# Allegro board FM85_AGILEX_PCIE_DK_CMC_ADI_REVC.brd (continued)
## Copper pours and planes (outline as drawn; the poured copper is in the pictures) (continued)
3P3V on L12_SIG4: 199.52,98.89 199.88,98.53 202.68,98.53 204.88,96.34 214.4,96.34 215.06,97.01 215.06,107.45 212.45,110.06 22.59,110.06 22.47,109.94 22.47,107.81 22.91,107.38 26.64,107.38 28.18,108.92 30.35,108.92 30.74,108.53 54.43,108.53 55.03,107.94 97.07,107.94 97.61,107.39 145.81,107.39 146.22,107.81 198.64,107.81 199.52,106.93
3P3V on L12_SIG4: 66.3,49.68 66.87,49.11 66.87,48.07 65.64,46.85 64.04,46.85 63.76,46.57 63.76,46.17 65.03,44.9 65.03,44.01 63.91,42.9 62.36,42.9 53.5,34.04 47.49,34.04 46.62,33.16 46.62,29.13 48.72,29.13 49.28,29.69 50.93,29.69 50.93,29.7 55.81,29.7 55.81,29.69 59.35,29.69 65.21,35.56 76.85,35.56 79.38,38.09 79.38,40.37 81.4,42.39 83.1,42.39 87.68,46.97 87.68,47.59 80.3,54.97 79.8,54.97 79.8,61.21 79.44,61.57 79.38,61.57 79.38,65.99 77.06,68.31 77.06,69.2 75.94,70.31 71.15,70.31 67.13,74.33 67.13,82.62 70.29,85.78 70.29,87.12 70.38,87.22 70.38,90.54 65.66,95.27 36.47,95.27 34.63,93.43 34.63,84.41 35.95,83.09 42.72,83.09 43.99,84.37 58.84,84.37 59.12,84.09 59.12,78.56 51,78.56 48.89,76.45 48.89,60.58 50.84,58.63 57.83,58.63 59.12,57.34 59.12,51.68 61.12,49.68
3P3V on L12_SIG4: 224.55,45.2 226.41,47.06 226.41,55.37 227.56,56.52 236.79,56.52 238.01,55.3 238.01,49.38 237.15,48.53 234.35,48.53 231.61,45.78 231.61,37.77 239.45,29.93 239.45,20.43 239.06,20.04 237.72,20.04 237.27,20.48 237.27,27.26 229.83,34.71 225.47,34.71 224.55,35.63
3P3V on L14_SIG5: 222.89,50.12 222.89,22.34 223.59,21.65 239.42,21.65 241.76,23.98 241.76,34.03 244.36,36.63 244.36,48.34 239.15,53.55 226.32,53.55
3P3V_AGND on TOP: 236.94,36.4 236.94,37.32 236.56,37.7 235.74,37.7 235.49,37.95 235.49,38.43 235.47,38.46 234.83,38.46 234.8,38.43 234.8,37.39 234.65,37.24 233.66,37.24 233.51,37.39 233.51,38.38 233.43,38.46 231.76,38.46 231.68,38.38 231.68,36.48 231.83,36.32 236.86,36.32
3P3V_STBY on TOP: 225.2,36.32 228.1,36.32 229.24,35.18 235.87,35.18 237.32,33.73 243.03,33.73 244.1,32.67 251.04,32.67 251.49,33.12 251.49,33.66 250.96,34.19 246.01,34.19 245.93,34.11 244.18,34.11 243.42,34.88 237.7,34.88 236.48,36.1 229.32,36.1 228.02,37.39 225.51,37.39 225.2,37.09
3P3V_STBY on TOP: 20.58,43.44 20.58,41.35 20.99,40.95 21.62,40.95 21.75,40.82 21.75,39.98 21.95,39.78 23.55,39.78 24.04,40.26 24.04,41.96 24.31,42.24 25.18,42.24 25.36,42.42 25.36,43.16 25.18,43.34 23.76,43.34 23.2,43.89 21.04,43.89
3P3V_STBY on BOTTOM: 21.32,47.15 21.32,44.2 20.66,43.54 20.66,41.28 22.64,39.3 23.38,39.3 23.38,39.96 23.5,40.08 23.5,47.12 23.35,47.27 21.44,47.27
3P3V_STBY on L05_SIG2: 251.85,99.39 241.31,109.93 13.59,109.93 13.57,109.91 12.46,109.91 11.93,109.38 11.93,43.17 15.06,40.04 27.73,40.04 29.72,42.03 29.72,58.86 28.33,60.25 28.33,62.56 26.86,64.02 26.93,64.09 26.93,104.09 30.49,107.65 39.25,107.65 39.63,107.27 92.59,107.27 93.86,108.54 167.9,108.54 169.04,107.39 195.03,107.39 195.18,107.24 195.18,93.78 193.28,91.87 168.13,91.87 167.6,91.34 167.6,88.75 167.68,88.66 202.36,88.66 203.61,87.41 209.88,87.41 210.78,86.51 210.78,84.88 211.5,84.16 214.21,84.16 214.56,84.52 214.56,90.25 211.14,93.67 206.05,93.67 205.25,94.47 205.25,103.82 206.05,104.61 208.15,104.61 208.54,104.22 227.72,104.22 229.5,106 242.07,106 249.56,98.5 249.56,82.63 248.42,81.49 242.7,81.49 238.64,77.42 238.64,72.21 240.04,70.82 242.83,70.82 243.65,70 243.65,30.91 244.2,30.36 244.2,29.35 238.35,23.51 217.19,23.51 213.33,19.65 202.14,19.65 201.52,20.27 198.85,20.27 198.4,19.82 198.4,18.88 196.48,16.96 196.48,15 196.65,14.84 224.14,14.84 225.58,16.28 243.64,16.28 251.85,24.49
3P3V_STBY on L12_SIG4: 229.19,96.07 232.72,96.07 232.98,96.32 232.98,104.79 233.45,105.26 233.45,106.62 233.03,107.04 229.19,107.04 228.94,106.78 228.94,96.32
3P3V_STBY on L14_SIG5: outline of 88 points within 2.04,11.13 77.53,86.1
3P3V_USBPHY on L09_PWR1: 19.82,35.26 1.66,35.26 1.28,34.88 1.28,14.56 1.66,14.18 19.7,14.18 20.2,14.68 20.2,34.88
3P3V_USBPHY on L12_SIG4: 6.05,33.81 6.05,29.92 8.87,27.1 8.87,22.46 11.77,19.56 19.69,19.56 20.68,20.55 20.68,25.58 29.29,34.19 36.46,34.19 37.14,34.88 37.14,36.1 37.1,36.13 37.1,37.41 36.39,38.12 30.4,38.12 27.16,34.88 26.32,34.88 22.74,31.3 20.68,31.3 17.03,34.95 7.2,34.95
CH01_RUN on L16_SIG6: 186.91,25.16 186.91,23.41 187.31,23.01 187.88,23.01 188.04,23.16 188.04,23.86 188.41,24.24 190.39,24.24 190.9,23.74 190.9,23.55 191.09,23.36 191.72,23.36 191.93,23.56 191.93,23.99 192.91,24.98 192.91,25.28 192.56,25.63 187.38,25.63
CH02_RUN on L03_SIG1: 208.77,98.33 208.77,97.38 209.02,97.13 211.04,97.13 211.2,97.28 212.25,97.28 212.41,97.13 214.87,97.13 215.08,97.34 215.84,97.34 216.05,97.13 216.86,97.13 217.54,96.46 218.09,96.46 218.39,96.76 218.39,97.16 217.99,97.55 217.65,97.55 217.14,98.06 217.14,98.34 217.1,98.38 216.46,98.38 216.35,98.27 216.35,98.03 216.17,97.85 214.94,97.85 214.67,97.58 213.32,97.58 213.06,97.84 213.06,98.24 212.95,98.35 212.69,98.35 212.56,98.22 212.56,98 212.43,97.87 211.13,97.87 210.95,97.7 209.35,97.7 209.3,97.75 209.3,98.36 209.22,98.44 208.87,98.44
COMP_0P8 on L12_SIG4: 70.05,72.87 70.05,72.56 71.52,71.09 75.81,71.09 75.81,71.5 74.98,72.33 71.17,72.33 70.52,72.99 70.17,72.99
FGT_AGND on BOTTOM: 38.13,106.73 38.13,105.9 38.36,105.67 43.01,105.67 44.91,103.76 45.52,103.76 45.68,103.91 45.68,106.12 44.91,106.89 38.28,106.89
FPGA_VCC on TOP: 155.27,92 161.55,92 161.98,91.57 161.98,31.65 161.14,30.81 142.76,30.81 142.37,31.19 87.64,31.19 85.39,33.44 85.39,89.91 86.88,91.39 146.78,91.39 147.62,90.55 147.62,90.51 148.01,90.12 154.62,90.12 154.93,90.44 154.93,91.67 ; 9 cut-outs
FPGA_VCC on BOTTOM: 119.01,34.5 119.01,32.34 118.88,32.21 117.61,32.21 117.48,32.34 117.48,34.5 117.61,34.62 118.88,34.62
FPGA_VCC on BOTTOM: 115.45,53.67 115.45,54.69 117.99,54.69 118.12,54.56 118.12,53.42 118.29,53.24 119.51,53.24 119.67,53.09 119.82,53.24 119.82,53.93 120.05,54.16 122.03,54.16 122.49,53.7 123.02,53.7 123.02,53.39 123.17,53.24 123.55,53.24 123.93,52.86 123.93,51.95 123.63,51.64 122.94,51.64 122.1,50.8 121.8,50.8 120.43,49.43 119.36,49.43 119.13,49.66 118.6,49.66 118.29,49.35 117.76,49.35 117.46,49.66 117,49.66 116.69,49.35 116.16,49.35 115.7,49.81 115.55,49.81 115.17,49.43 114.56,49.43 114.18,49.81 113.88,49.81 113.42,49.35 113.04,49.35 112.5,49.89 112.5,50.65 112.81,50.96 113.65,50.96 113.88,51.18 113.88,51.41 113.57,51.72 113.57,52.17 113.8,52.4 114.18,52.4
FPGA_VCC on BOTTOM: 144.91,71.33 144.91,72.6 144.3,73.21 144.3,89.92 154.62,89.92 156.83,92.13 158.71,92.13 158.99,91.85 158.99,90.58 159.11,90.45 159.11,30.99 157.3,30.99 156.91,31.38 154.56,31.38 154.36,31.57 154.36,38.38 150.76,41.99 150.76,45.16 151.26,45.67 154.19,45.67 154.44,45.93 154.44,49.46 152.79,51.11 152.79,56.34 152.53,56.59 151.77,56.59 151.39,56.97 151.39,64.09 150.76,64.72 149.74,64.72 149.36,65.1 149.36,67.52 148.34,68.53 148.34,70.56 147.94,70.97 145.27,70.97
FPGA_VCC on BOTTOM: 112.5,54.16 112.5,65.05 111.67,65.89 110.9,65.89 110.07,66.73 109.91,66.73 109.53,66.35 109.53,64.37 108.76,64.37 108.76,62.93 109.38,62.31 109.38,62 108.69,61.32 108.69,59.95 107.93,59.18 107.93,58.8 108.16,58.58 108.16,58.27 107.93,58.04 107.93,55.15 108.31,54.77 108.31,54.08 107.93,53.7 107.93,52.94 109.53,51.34 111.44,51.34 113.42,53.32 113.42,53.7 113.27,53.85 112.81,53.85
FPGA_VCC on BOTTOM: 131.58,86.76 129.8,86.76 129.8,85.04 130.06,84.79 131.33,84.79 131.58,85.04
FPGA_VCC on BOTTOM: 120.53,55.07 120.53,64.59 120.45,64.67 119.82,64.67 119.21,65.28 119.21,65.36 120.12,66.27 120.5,66.27 121.04,66.8 121.5,66.8 121.88,67.19 122.1,67.19 122.41,67.49 123.32,67.49 124.01,66.8 126.19,66.8 126.19,63.47 125.94,63.22 123.98,63.22 123.61,62.85 123.61,61.88 123.95,61.88 125.05,60.78 125.05,59.75 123.76,58.46 123.76,57.79 123.88,57.67 124.09,57.67 124.84,56.92 124.84,54.45 124.39,54 124.16,54 123.63,54.54 121.72,54.54 121.55,54.71 120.89,54.71
FPGA_VCC on BOTTOM: 117.36,64.09 114.93,64.09 114.77,64.25 114.77,64.62 114.52,64.87 114.52,64.9 114.48,64.9 113.49,65.89 112.96,65.89 112.5,66.35 112.28,66.35 111.74,66.88 111.36,66.88 111.21,67.03 111.21,67.34 111.89,68.02 112.81,68.02 114.18,69.4 114.94,69.4 115.25,69.09 115.93,69.09 116.16,69.32 116.54,69.32 116.77,69.09 117.38,69.09 117.76,69.47 118.07,69.47 118.52,69.01 118.98,69.01 119.29,69.32 119.74,69.32 120.05,69.01 120.5,69.01 120.89,69.4 121.34,69.4 121.57,69.17 121.57,69.01 121.34,68.79 121.34,68.02 121.11,67.8 120.66,67.8 120.58,67.72 120.58,67.49 120.5,67.41 119.9,67.41 119.82,67.34 119.82,67.26 119.06,66.5 118.37,66.5 118.22,66.35 118.22,66.04 117.36,65.18
FPGA_VCC on L09_PWR1: 170.7,91.52 170.7,44.1 158.66,32.06 110.57,32.06 110.5,32.13 110.5,37.04 108.21,39.32 108.21,59.01 108.97,59.77 108.97,65.99 108.59,66.37 105.67,66.37 105.29,66.75 105.29,74.88 96.67,83.5 96.67,86.69 97.4,87.41 106.38,87.41 107.32,86.47 107.32,79.99 110.37,76.94 110.37,69.47 110.52,69.32 123.48,69.32 123.86,69.7 123.86,89.08 126.68,91.9 170.31,91.9
GXR_AGND on BOTTOM: 210.19,36.4 210.19,32.51 209.96,32.29 208.74,32.29 208.44,32.59 208.44,33.96 208.29,34.11 208.29,34.34 208.44,34.5 209.13,34.5 209.32,34.69 209.32,36.52 210.34,37.54 210.57,37.54 210.8,37.32 210.8,37.01
HSSI_GXF_AGND on TOP: 69.63,72.06 69.63,70.39 69.7,70.31 71.58,70.31 71.66,70.39 71.66,72.06 71.52,72.2 69.77,72.2
HSSI_GXF_AGND on L14_SIG5: 75.01,67.11 75.01,67.12 75.07,67.18 75.58,67.18 76.58,68.18 76.58,71.64 75.75,72.46 71.64,72.46 71.64,72.37 69.94,72.37 69.9,72.41 68.43,72.41 68.05,72.03 68.05,67.96 68.89,67.11
IIN-_0 on TOP: 189.08,43 188.6,42.52 188.6,38.41 188.81,38.2 193.1,38.2 193.12,38.23 195.51,38.23 195.66,38.38 195.66,41 194.67,41.99 194.67,42.95 194.49,43.13 193.58,43.13 193.45,43
IIN-_0 on BOTTOM: 186.8,43.18 186.72,43.11 186.72,41.89 187.13,41.48 187.13,39.37 186.72,39.37 186.57,39.22 186.57,38.31 186.65,38.23 188.4,38.23 188.63,38 195.51,38 195.82,38.31 196.4,38.31 196.45,38.36 196.45,43.36 196.25,43.56 195.94,43.56 195.79,43.41 195.79,42.42 195.56,42.19 194.8,42.19 194.62,42.37 194.62,43.18
INTVCC4 on BOTTOM: 42.48,102.39 42.48,104.14 41.64,104.98 38.06,104.98 37.98,104.9 37.29,104.9 37.29,105.9 37.07,106.12 37.07,106.5 37.14,106.58 37.75,106.58 37.9,106.43 37.9,105.82 38.28,105.44 43.09,105.44 43.31,105.21 43.31,102.39 43.24,102.31 42.55,102.31
INTVCC5 on BOTTOM: 205.85,32.06 205.85,31.52 206.61,30.76 211.03,30.76 212.17,31.91 212.17,37.39 211.26,38.31 209.81,38.31 209.51,38 208.97,38 208.97,37.32 208.59,36.93 208.13,36.93 208.13,36.32 208.74,36.32 210.12,37.7 211.03,37.7 211.11,37.62 211.11,32.67 210.5,32.06 206.84,32.06 206.61,32.29 206.08,32.29
INTVCC6 on BOTTOM: 51.24,106.58 51.24,105.97 51.39,105.82 51.39,104.26 52.36,103.29 56.44,103.29 56.57,103.15 56.57,102.54 57.11,102.54 57.18,102.62 57.18,104.14 56.88,104.45 53.37,104.45 51.92,105.9 51.92,106.5 51.77,106.66 51.32,106.66
IO_1P8V on BOTTOM (solid shape): 41.92,43.64 41.92,42.62 41.79,42.5 40.39,42.5 40.27,42.62 40.27,43.64 40.39,43.77 41.79,43.77
IO_1P8V on BOTTOM (solid shape): 55.71,43.8 55.71,43.17 55.58,43.04 54.69,43.04 54.57,43.17 54.57,43.8 54.69,43.93 55.58,43.93
IO_1P8V on BOTTOM: 108.86,84.53 109.75,85.42 110.24,85.42 110.37,85.3 110.37,83.57 109.94,83.14 107.17,83.14 107.17,82.81 106.56,82.81 106.56,83.51 106.1,83.51 106.1,82.81 105.57,82.81 105.57,83.51 105.11,83.51 105.11,82.81 104.58,82.81 104.58,83.51 104.12,83.51 104.12,82.81 103.59,82.81 103.59,83.51 103.13,83.51 103.13,82.81 102.6,82.81 102.6,83.61 102.22,83.61 102.22,82.88 101.68,82.88 101.68,83.98 102.24,84.53
IO_1P8V on BOTTOM: 73.34,35.72 73.34,34.27 72.8,33.73 72.8,31.91 72.88,31.83 74.1,31.83 74.18,31.91 74.18,34.65 73.95,34.88 73.95,35.72 73.87,35.79 73.41,35.79
IO_1P8V on BOTTOM: 51.66,20.25 51.66,21.14 51.68,21.16 52.69,21.16 52.76,21.08 52.76,20.15 52.66,20.05 51.86,20.05
IO_1P8V on BOTTOM: 67.67,38.92 68.31,38.92 68.79,38.43 68.97,38.43 69.12,38.59 69.12,41.68 68.99,41.81 67.6,41.81 67.49,41.71 67.49,39.09
IO_1P8V on BOTTOM: 60.33,29.92 60.33,30.25 60.46,30.38 61.73,30.38 61.91,30.2 61.91,28.49 61.76,28.34 60.51,28.34 60.25,28.59 60.25,29.84
IO_1P8V on L03_SIG1: 1.91,78.69 2.29,78.31 6.08,78.31 6.77,79 6.77,96.25 12.3,101.78 16.04,101.78 19.9,105.63 19.9,108.07 19.8,108.16 16.96,108.16 15.23,106.43 11.94,106.43 1.91,96.4
IO_1P8V on L05_SIG2: 48.14,33.99 52.2,33.99 53.73,32.46 53.73,20.91 52.92,20.09 49.03,20.09 47.63,21.49 47.63,33.48
IO_1P8V on L07_SIG3: outline of 84 points within 40.42,18.61 125.74,85.55 ; 1 cut-out
IO_1P8V on L10_PWR2: 43.57,21.26 42.61,20.29 40.33,20.29 38.47,18.44 38.47,15.67 40.47,13.68 45.05,13.68 45.78,14.41 51.84,14.41 52.87,15.44 52.87,20.8 52.4,21.26
IO_1P8V on L10_PWR2: 126.42,49.22 124.31,49.22 123.97,48.88 123.97,48.71 133.3,39.38 135.66,39.38 138.76,36.28 138.76,33.7 139.32,33.14 140.73,33.14 141.67,34.09 141.67,41.78 140.32,43.13 132.51,43.13
IO_1P8V on L16_SIG6: 3.31,87.2 1.66,87.2 1.15,86.69 1.15,56.89 13.49,44.55 28.47,44.55 32.2,40.82 32.22,40.82 32.22,39.93 32.6,39.55 41.21,39.55 41.79,40.13 41.79,43.56 41.54,43.82 33.7,43.82 29.07,48.45 16.4,48.45 3.69,61.17 3.69,86.82
IO_1P8V_SI53254_1 on BOTTOM (solid shape): 57.36,43.8 57.36,43.17 57.23,43.04 56.34,43.04 56.22,43.17 56.22,43.8 56.34,43.93 57.23,43.93
IO_1P8V_SI53254_1 on L03_SIG1: 59.46,40.26 60.19,39.54 60.19,35.86 59.83,35.51 55.58,35.51 54.94,36.15 54.94,42.31 56.5,43.87 58.72,43.87 59.46,43.13
IO_1P8V_SI53254_1 on L14_SIG5: 56.22,43.72 59.22,43.72 62.03,40.91 62.03,39.2 61.88,39.05 61.01,39.05 59.69,40.37 57.74,40.37 55.86,42.24 55.86,43.37
IO_3P3V on BOTTOM: 204.93,89.06 206.84,89.06 206.92,88.98 208.97,88.98 209.13,89.13 209.13,89.74 209.2,89.82 209.66,89.82 209.73,89.74 209.73,88.52 209.66,88.45 206.53,88.45 206.31,88.67 204.93,88.67
IO_3P3V on BOTTOM: 41.51,78.82 34.04,78.82 32.9,79.96 32.9,83.39 33.15,83.39 33.15,82.5 33.66,81.99 33.66,81.1 33.92,80.85 35.44,80.85 35.95,81.36 37.09,81.36 37.22,81.49 37.22,82.58 37.26,82.63 41.54,82.63 42.43,83.52 42.43,86.85 42.64,87.07 43.95,87.07 44.2,87.33 44.2,88.98 44.35,89.13 46.37,89.13 46.37,83.71 45.54,83.71 45.09,83.26 45.09,82.37 44.97,82.25 43.7,82.25 43.57,82.12 43.57,79.2 43.7,79.07 44.46,79.07 44.71,79.33 44.71,79.71 44.97,79.96 46.24,79.96 46.24,77.68 45.96,77.4 45.75,77.4 45.68,77.32 45.68,75.49 45.6,75.42 45.22,75.42 45.14,75.49 45.14,77.32 45.07,77.4 43.78,77.4 43.7,77.32 43.7,75.42 43.62,75.34 42.93,75.34 42.86,75.42 42.86,77.47 ; 2 cut-outs
IO_3P3V on BOTTOM: 45.98,58.75 45.35,58.75 45.09,58.5 45.09,57.61 44.97,57.48 43.7,57.48 43.57,57.36 43.57,54.43 43.7,54.31 44.46,54.31 44.71,54.56 44.71,54.94 44.97,55.2 46.37,55.2 46.37,52.91 43.06,52.91 42.81,53.16 42.81,64.09 43.06,64.34 46.24,64.34 46.24,59.01 ; 2 cut-outs
IO_3P3V on L03_SIG1: 52.08,11.13 58.81,11.13 59.47,11.79 59.47,12.25 59.44,12.27 60.84,13.67 60.84,17.2 58.17,19.87 52.31,19.87 50.86,18.42 50.86,16.13 54.31,16.13 55.13,15.32 55.13,14.18 54.62,13.67 52.99,13.67 51.82,12.5 51.82,11.38
IO_3P3V on L05_SIG2: 56.4,32.97 55.89,32.46 54.74,32.46 52.71,34.5 48.9,34.5 48.14,35.26 48.14,43.89 44.71,47.32 44.71,49.48 42.12,52.07 42.12,63.1 44.38,65.36 58.08,65.36 59.63,63.8 59.63,50.49 56.4,47.25
IO_3P3V on L10_PWR2: 48.39,47.37 48.39,47.36 48.41,47.34 48.41,36.51 49,35.92 56.26,35.92 58.59,33.59 58.59,17.63 56.81,15.85 54.05,15.85 53.37,16.53 53.37,21.19 52.86,21.69 43.46,21.69 42.61,20.84 40.07,20.84 37.93,18.7 37.93,16.01 36.53,14.62 5.6,14.62 2.3,17.91 2.3,107.8 4.86,110.35 30.26,110.35 31.16,109.45 31.16,95.91 32.99,94.08 44.74,94.08 48.39,90.42
IO_3P3V on L12_SIG4: 31.38,92.53 15.63,92.53 13.85,94.31 13.85,106.38 15.18,107.7 15.18,109.71 15.47,110 20.9,110 20.9,110.01 21.06,110.01 21.24,109.83 21.24,109.29 21.16,109.21 20.56,109.21 20.12,108.78 18.33,108.78 17.93,108.38 17.93,104.85 27.96,94.83 31.23,94.83 31.67,94.38 31.67,92.83
IO_3P3V on L16_SIG6: 62.82,108.54 61.51,107.23 54.58,107.23 53.27,108.54 22.99,108.54 22.61,108.16 22.61,106.25 22.23,105.87 19.82,105.87 19.57,106.12 19.57,109.43 20.2,110.06 232.8,110.06 232.84,110.02 247.97,110.02 252.64,105.36 252.64,36.25 252.03,35.64 245.88,35.64 245.12,36.4 245.12,49.13 245.27,49.28 246.69,49.28 246.92,49.05 246.92,45.16 247.23,44.86 249.66,44.86 250.27,45.47 250.27,56.59 242.58,64.29 242.58,94.06 229.75,106.89 222.08,106.89 218.57,103.38 218.42,103.38 218.12,103.08 218.12,90.43 216.06,88.37 208.67,88.37 208.06,88.98 208.06,99.72 208.07,99.74 208.07,105.32 207.17,106.22 204.2,106.22 201.89,108.54
LT4625_INTVCC on BOTTOM: 231.76,64.52 231.76,65.28 231.45,65.59 228.02,65.59 227.57,65.13 227.57,58.58 228.02,58.12 234.88,58.12 235.26,58.5 235.26,63.45 235.41,63.6 236.02,63.6 236.1,63.68 236.1,64.21 235.95,64.37 235.03,64.37 234.88,64.21 234.88,63.68 234.5,63.3 233.97,63.3 233.59,62.92 233.59,60.1 233.28,59.79 230.92,59.79 230.39,59.26 229.24,59.26 229.17,59.34 229.17,60.02 229.09,60.1 228.63,60.1 228.56,60.18 228.56,64.21 228.71,64.37 231.6,64.37
LTM_INTVCC1 on L14_SIG5: 73.74,38.31 70.06,38.31 69.91,38.15 69.91,36.86 69.83,36.78 68.69,36.78 68.31,36.4 68.31,31.42 68.73,30.99 71.12,30.99 73.94,33.81 73.94,38.11
M10_1V2_VCCDPLL on BOTTOM: 20.69,30 21.37,30 21.52,30.15 21.52,31.75 21.37,31.9 20.79,31.9 20.66,31.77 20.66,31.44 20.45,31.24 20.45,30.24
M10_1V2_VCCDPLL on L09_PWR1: 39.76,19.64 39.76,35 39.5,35.26 35.69,35.26 35.31,34.88 35.31,21.8 34.68,21.16 28.58,21.16 27.57,22.18 27.19,22.18 26.8,22.56 26.8,30.3 26.3,30.81 22.99,30.81 22.11,31.7 20.71,31.7 20.71,18.92 21.22,18.41 24.63,18.41 24.65,18.42 38.54,18.42
MAX10_VCCA_2.5V on BOTTOM: 23.4,34.27 22.66,34.27 22.36,34.57 21.83,34.57 21.6,34.8 21.6,35.41 21.67,35.49 23.27,35.49 23.5,35.26 23.5,34.37
MAX10_VCCA_2.5V on L09_PWR1: 34.93,21.92 34.55,21.54 28.71,21.54 27.69,22.56 27.31,22.56 27.19,22.68 27.19,30.43 26.42,31.19 23.12,31.19 21.34,32.97 21.34,35.42 21.64,35.72 34.5,35.72 34.93,35.29
PCIE_EP_3P3V on TOP (solid shape): 53.33,8.61 53.33,6.15 52.95,5.78 52.95,2.6 52.35,2.6 52.35,5.77 52.08,6.05 52.08,6.18 52.08,8.59 52.2,8.71 53.22,8.71
PCIE_EP_3P3V on BOTTOM (solid shape): 53.73,8.71 53.73,7.32 54.95,6.09 54.95,2.6 53.35,2.6 53.35,5.66 52.81,6.2 52.81,6.22 52.78,6.32 52.72,6.41 52.08,7.05 52.08,8.18 52.14,8.28 52.16,8.39 52.16,8.81 52.3,8.94 53.5,8.94
PCIE_EP_12V on TOP (solid shape): 48.93,9.05 48.93,6.96 48.7,6.73 48.52,6.73 48.22,6.43 48.22,5.92 47.95,5.66 47.95,2.6 45.45,2.6 45.45,5.79 45.65,6 45.65,8.89 46.08,9.32 48.65,9.32
PCIE_EP_12V on BOTTOM (solid shape): 48.93,8.82 48.93,6.96 48.7,6.73 48.52,6.73 48.22,6.43 48.22,5.92 47.95,5.66 47.95,2.6 46.35,2.6 46.35,5.8 46.13,6.02 46.13,8.84 46.34,9.05 48.7,9.05
PCIE_EP_12V on TOP: 210.19,73.03 210.19,68.94 209.89,68.63 207.22,68.63 206.66,69.19 206.66,74.2 206.86,74.4 209.66,74.4 210.47,75.21 211.97,75.21 211.97,73.36 211.91,73.29 210.46,73.29
PCIE_EP_12V on BOTTOM: 210.12,68.48 207.73,68.48 207.68,68.53 207.68,72.11 207.4,72.39 207.4,73.99 207.47,74.07 210.52,74.07 210.7,73.89 210.7,72.01 210.88,71.83 211.67,71.83 211.67,71.58 210.73,71.58 210.7,71.55 210.7,69.07
PCIE_EP_12V on L07_SIG3: 212.18,76.61 212.18,82.02 216.38,86.21 216.38,88.85 216.27,88.96 211.54,88.96 209.91,87.33 208.11,87.33 206.69,85.91 206.69,71.24 207.3,70.63 209.95,70.63 210.6,71.28 210.6,75.03
PCIE_EP_12V on L09_PWR1: 205.34,77.35 234.73,77.35 236.1,75.97 236.1,61.37 239.97,57.5 239.97,51.61 242.07,49.52 242.07,43.54 241.48,42.96 241.48,39.22 242.07,38.64 242.07,32.67 242.91,31.83 242.91,13.64 242.65,13.38 140.78,13.38 140.05,13.27 139.39,12.93 133.87,12.93 130.55,9.62 130.2,9.57 129.86,9.45 56.14,9.45 55.31,8.62 55.31,6.27 54.37,5.33 46.12,5.33 45.63,5.83 45.63,10.92 45.55,11.57 45.3,12.17 45.3,14.84 47.48,17.02 47.48,17.05 48.38,17.95 209.19,17.95 214.54,23.29 214.54,30.91 215.3,31.68 229.93,31.68 233.74,35.49 233.71,35.51 233.71,46.15 238.22,50.66 238.22,55.95 236.96,57.2 229.62,57.2 227.87,58.96 227.87,62.11 227.82,62.11 227.82,68.15 226.75,69.22 204.68,69.22 204.32,69.57 204.32,76.33
PCIE_EP_12V on L10_PWR2: 46.27,5.92 46.27,10.92 46.26,11.16 46.24,11.4 46.24,13.55 46.59,13.9 52.26,13.9 53.55,15.19 55.8,15.19 56.05,14.95 56.05,13.33 56.6,12.78 58.2,12.78 58.97,13.54 58.98,13.54 60.61,15.17 125.34,15.17 125.39,15.23 132.13,15.23 133.09,16.2 172.34,16.2 173.5,17.35 180.16,17.35 180.65,16.87 197.92,16.87 198.68,16.11 199.46,16.11 199.77,15.8 208.27,15.8 211.25,18.78 211.25,56.64 212.12,57.51 235.41,57.51 237.09,59.18 237.09,61.85 235.87,63.07 232.06,63.07 228.48,66.65 228.48,66.83 224.89,70.42 207.86,70.42 207.22,71.06 207.22,73.59 207.53,73.89 209.71,73.89 212.86,77.04 233.69,77.04 235.47,75.26 235.47,65.97 236.46,64.98 241.82,64.98 242.73,64.06 242.73,60.1 239.76,57.13 239.76,51.56 241.65,49.67 241.65,14.26 241.41,14.02 223.25,14.02 222.77,13.54 220.45,13.54 219.97,14.02 140.78,14.02 138.64,13.14 137.76,11 137.76,10.26 130.66,10.26 128.8,9.48 128.03,7.62 128.03,6.3 59.37,6.3 59.37,7.45 57.15,9.67 54.93,7.45 54.93,6.17 54.55,5.79 46.4,5.79
PCIE_EP_12V on L12_SIG4: 243.85,69.93 244.74,69.93 244.86,69.8 244.86,67.01 243.34,65.48 217.3,65.48 213.46,69.33 208.3,69.33 207.42,70.21 207.42,73.97 207.58,74.12 209.28,74.12 209.48,73.92 209.48,73.15 209.91,72.72 213.67,72.72 218.4,68 243.06,68 243.72,68.66 243.72,69.8
QSFPDD0_VCC on BOTTOM: 57.67,81.87 57.92,82.12 57.92,82.72 57.67,82.97 56.8,82.97 56.38,83.39 54.74,83.39 54.49,83.64 54.49,85.55 54.24,85.8 54.24,89.61 53.73,90.12 48.01,90.12 47.25,89.36 47.25,87.45 47.76,86.95 52.08,86.95 52.46,86.57 52.46,82.12 52.71,81.87
QSFPDD0_VCCR on BOTTOM: 51.7,80.6 52.08,80.98 52.08,81.87 49.66,81.87 48.52,83.01 48.52,86.06 47.12,86.06 47.12,80.6
QSFPDD0_VCCT on BOTTOM: 47.51,80.22 47.25,79.96 47.25,77.93 47.38,77.8 48.65,77.8 48.78,77.93 48.78,78.62 49,78.84 52.23,78.84 52.48,78.59 53.6,78.59 53.6,79.74 54.1,80.24 57.69,80.24 57.92,80.47 57.92,81.23 57.67,81.49 53.09,81.49 51.82,80.22
QSFPDD1_VCC on BOTTOM: 53.09,57.1 57.67,57.1 57.92,57.36 57.92,57.86 57.67,58.12 57.03,58.12 56.52,58.63 55.28,58.63 55.13,58.47 54.67,58.47 54.49,58.65 54.49,61.45 54.21,61.72 54.21,62.15 53.11,63.25 53.11,64.15 51.9,65.36 48.14,65.36 47.25,64.47 47.25,62.31 52.08,62.31 52.46,61.93 52.46,59.13 52.97,58.63 52.97,57.23
QSFPDD1_VCCR on BOTTOM: 51.7,55.83 51.95,56.09 51.95,56.85 51.63,57.17 48.77,57.17 48.52,57.41 48.52,61.29 47.12,61.29 47.12,55.83
QSFPDD1_VCCT on BOTTOM: 47.43,55.45 47.17,55.19 47.17,52.92 48.53,52.92 48.78,53.16 48.78,53.8 53.73,53.8 53.73,54.82 54.36,55.45 58.17,55.45 58.43,55.7 58.43,56.47 58.17,56.72 53.09,56.72 51.82,55.45
SI5391_1P8V_VDDO on TOP: 58.07,28.93 58.07,28.17 58.15,28.1 59.6,28.1 59.93,28.43 59.93,28.86 59.75,29.03 58.17,29.03
SI5391_1P8V_VDDO on BOTTOM: 58.81,27.76 58.81,29.92 58.94,30.05 59.7,30.05 59.89,29.86 59.89,27.73 59.74,27.58 58.99,27.58
SI5391_1P8V_VDDO on L07_SIG3: 60,26.23 60,29.62 59.73,29.89 59.43,29.89 59.31,29.77 59.31,29.5 57.96,28.15 54.57,28.15 54.32,27.89 54.32,27.23 53.98,26.9 52.88,26.9 52.56,27.22 52.56,27.73 52.15,28.15 51.19,28.15 50.69,27.66 50.69,27.21 50.82,27.08 51.35,27.08 51.76,26.67 51.76,25.65 51.42,25.31 50.8,25.31 50.69,25.2 50.69,23.61 50.78,23.52 53.36,23.52 54.37,24.53 57.76,24.53 57.78,24.52 58.29,24.52
SI5391_2P5V_VDDO on BOTTOM: 59.25,22.3 57.92,22.3 57.75,22.47 57.75,24.08 59.06,24.08 59.25,23.89
SI5391_2P5V_VDDO on L07_SIG3: 51.25,28.46 52.01,28.46 52.82,27.65 52.82,27.38 53.02,27.17 53.71,27.17 53.98,27.44 53.98,27.89 53.98,27.9 53.98,28.14 54.3,28.46 57.75,28.46 58.51,29.22 58.51,30.05 58.23,30.34 51.19,30.34 49.84,28.99 49.84,22.73 51.12,21.45 56.41,21.45 57.4,22.44 58.23,22.44 58.51,22.72 58.51,23.92 58.26,24.17 54.39,24.17 53.55,23.33 50.61,23.33 50.49,23.45 50.49,25.27 50.68,25.46 51.17,25.46 51.54,25.83 51.54,26.57 51.22,26.88 50.76,26.88 50.58,27.06 50.58,27.79
SI5391_VDD on BOTTOM: 51.19,22.68 50.93,22.94 49.79,22.94 49.54,22.68 49.54,20.77 49.66,20.65 51.16,20.65 51.19,20.68
SI5391_VDD on L03_SIG1: 51.47,27.87 51.47,23.52 50.63,22.68 50.63,21.77 50.9,21.5 52.62,21.5 57.16,26.04 57.33,26.04 58.33,27.03 58.33,27.64 58.17,27.79 55.81,27.79 54.82,26.8 52.84,26.8 52.38,27.26 52.38,27.94 52.23,28.1 51.7,28.1
SI5391_VDDA on BOTTOM: 57.67,19.89 56.14,19.89 56.14,18.87 56.4,18.62 57.41,18.62 57.67,18.87
SW_U120_FPGA_VCC on TOP: 169.3,88.47 169.65,88.12 169.65,85.22 169.49,85.05 168.2,85.05 167.92,84.77 167.92,83.44 168.07,83.29 169.49,83.29 169.58,83.2 169.58,79.94 169.43,79.78 162.95,79.78 162.5,80.23 162.5,87.63 162.89,88.02 166.74,88.02 167.19,88.47
SW_U121_FPGA_VCC on TOP: 169.43,74.45 169.7,74.17 169.7,71.07 169.65,71.02 168.23,71.02 168.1,70.89 168.1,69.45 168.26,69.29 169.68,69.29 169.7,69.27 169.7,66.07 169.5,65.86 162.82,65.86 162.49,66.2 162.49,74.26 162.68,74.45
SW_U125_FPGA_VCC on TOP: 169.22,60.73 169.63,60.33 169.63,57.01 169.46,56.85 168.28,56.85 168.19,56.75 168.19,55.63 168.37,55.45 169.53,55.45 169.76,55.22 169.76,52.15 169.22,51.62 162.72,51.62 162.49,51.84 162.49,60.53 162.69,60.73
SW_U126_FPGA_VCC on TOP: 169.22,45.72 169.55,45.39 169.55,42.29 169.44,42.18 168.24,42.18 168,41.94 168,40.74 168.23,40.52 169.53,40.52 169.6,40.44 169.6,37.37 169.32,37.09 162.7,37.09 162.48,37.32 162.48,45.4 162.8,45.72
VOSNS0_VCCR on L03_SIG1: 191.52,84.25 191.52,78.62 191.75,78.39 192.59,78.39 192.82,78.62 192.82,84.33 192.67,84.48 191.75,84.48
N17328275 on BOTTOM: 193.78,98.94 193.78,94.87 194.01,94.64 195.28,94.64 195.46,94.47 195.46,94.01 195.56,93.91 196.04,93.91 196.15,94.01 196.15,94.74 195.56,95.33 195.56,97.51 196.04,98 196.04,98.81 195.84,99.01 193.86,99.01
N31257069 on TOP (solid shape): 55.13,8.46 55.13,5.92 54.95,5.75 54.95,2.6 54.35,2.6 54.35,5.8 53.98,6.17 53.98,8.46 54.24,8.71 54.87,8.71
N31257069 on BOTTOM (solid shape): 54.87,9.48 55.13,9.22 55.13,7.44 54.87,7.19 54.24,7.19 53.98,7.44 53.98,9.1 54.49,9.6 54.49,10.87 54.87,10.87
N31314957 on TOP: 231.6,60.33 231.6,59.64 231.3,59.34 231.3,57.36 231.38,57.28 232.67,57.28 232.75,57.36 232.75,59.11 232.21,59.64 232.21,60.33 232.14,60.4 231.68,60.4
N31416063 on BOTTOM: 217.56,85.68 217.56,87.07 217.18,87.45 214.26,87.45 214.25,87.45 213.6,87.45 213.24,87.09 213.24,85.93 213.49,85.68 213.49,85.3 213.62,85.17 214.13,85.17 214.26,85.3 214.26,86.31 214.51,86.57 215.15,86.57 215.27,86.44 215.27,86.18 215.78,85.68
N40710582 on TOP: 202.57,36.65 202.17,36.65 201.66,37.16 199.6,37.16 199.52,37.09 199.52,33.51 199.83,33.2 201.51,33.2 202.17,33.86 202.57,33.86
N40814737 on TOP: 195.46,107.21 195.46,100.66 196.93,100.66 196.93,107.21
N40814737 on BOTTOM: 193.83,106.48 193.83,102.52 193.85,102.5 193.85,102.25 193.96,102.14 195.26,102.14 195.27,102.12 196.04,102.12 196.51,102.59 196.51,106.23 196.31,106.43 196.1,106.43 196.04,106.48
N41064896 on TOP (solid shape): 40.39,98.75 40.4,98.69 40.42,98.63 40.42,98.45 40.55,98.33 41.33,98.33 41.79,97.87 41.79,96.09 41.49,95.79 36.71,95.79 36.28,96.22 36.28,97.92 36.81,98.45 37.5,98.45 37.62,98.58 37.62,98.63 37.64,98.69 37.65,98.75 37.65,98.96 40.39,98.96
N45052102 on TOP (solid shape): 54.46,98.81 54.46,98.79 54.54,98.62 54.71,98.54 54.73,98.54 55.03,98.25 55.03,96 54.86,95.84 51.33,95.84 50.27,95.84 49.84,96.27 49.84,97.97 50.38,98.5 51.06,98.5 51.1,98.54 51.47,98.54 51.65,98.62 51.72,98.8 51.72,99.01 54.26,99.01
N46986379 on TOP (solid shape): 252.98,17.17 252.78,15.32 251.77,13.75 246.55,13.75 245.37,14.93 246.65,19.91 251.78,19.55 252.1,19.5 252.28,19.78 252.28,35.64 252.48,35.84 252.48,48.97 252.98,48.97
N46986379 on TOP (solid shape): 248.55,110.13 251.93,108.91 252.98,105.48 252.98,67.39 252.28,67.39 252.28,102.68 252.02,103.08 251.54,103.02 247.91,102.29 245.22,104.85 245.22,106.86 248.42,110.06
N46986379 on BOTTOM (solid shape): 248.55,110.13 251.93,108.91 252.98,105.48 252.98,17.17 252.78,15.32 251.77,13.75 246.55,13.75 245.37,14.93 246.65,19.91 251.78,19.55 252.1,19.5 252.28,19.78 252.28,47.83 252.36,47.91 252.36,58.17 252.28,58.25 252.28,102.68 252.02,103.08 251.54,103.02 247.76,102.33 245.14,105.13 244.49,105.13 243.64,105.98 241.11,105.98 240.95,106.14 240.95,107.71 241.17,107.93 245.04,107.93 247.23,110.13
N46986379 on L03_SIG1 (solid shape): 248.55,110.13 251.93,108.91 252.98,105.48 252.98,17.17 252.78,15.32 251.77,13.75 246.55,13.75 245.37,14.93 246.65,19.91 251.78,19.55 252.1,19.5 252.28,19.78 252.28,102.68 252.02,103.08 251.54,103.02 247.91,102.29 245.22,104.85 245.63,107.77 247.66,109.81
N47814473 on BOTTOM: 65.31,41.99 67.37,41.99 67.55,42.17 67.55,43.87 67.83,44.15 68.33,44.15 68.54,44.35 68.54,45.11 68.71,45.29 68.71,46.94 67.19,46.94 66.94,46.69 66.94,45.42 65.16,43.64 65.16,42.14
N47990323 on L05_SIG2: 65.06,39.23 65.06,37 66.17,35.89 70.61,35.89 70.77,36.04 70.77,36.47 71.02,36.73 71.43,36.73 71.74,36.42 71.74,35.95 71.84,35.85 72.37,35.85 72.62,36.1 72.62,38 72.31,38.31 68.69,38.31 67.44,39.56 65.39,39.56
N48264639 on L14_SIG5: 180.71,25.72 180.71,23.23 178.68,21.2 178.68,14.93 178.94,14.68 179.84,14.68 180.18,15.01 180.18,20.99 182.09,22.9 189.12,22.9 189.37,23.16 189.37,25.26 189.02,25.61 188.52,25.61 188.23,25.32 188.23,24.56 187.97,24.31 185.86,24.31 185.45,24.71 185.45,25.74 185.01,26.18 184.23,26.18 183.88,25.83 183.88,24.67 183.59,24.38 181.69,24.38 181.53,24.53 181.53,25.79 181.48,25.84 180.83,25.84
N48264690 on L14_SIG5: 181.93,27.42 181.93,25.11 182.23,24.81 183.26,24.81 183.27,24.82 183.3,24.82 183.49,25.01 183.49,26.11 183.89,26.51 185.3,26.51 185.71,26.1 185.71,24.96 186.03,24.64 187.77,24.64 187.94,24.8 187.94,25.41 188.3,25.77 189.16,25.77 189.65,25.28 189.65,24.59 189.81,24.42 193.8,24.42 194.21,24.83 194.21,26.82 193.61,27.42
N48264698 on L16_SIG6: 180.11,24.47 180.11,21.25 180.56,20.8 194.17,20.8 194.62,21.25 194.62,23.96 194.43,24.16 192.33,24.16 192.07,23.9 192.07,23.47 191.79,23.19 190.96,23.19 190.67,23.49 190.67,23.69 190.29,24.07 188.49,24.07 188.26,23.84 188.26,23.21 187.85,22.8 186.94,22.8 186.55,23.19 186.55,24.04 186.19,24.39 180.76,24.39 180.53,24.63 180.27,24.63
N48270066 on L05_SIG2: 206.09,97.27 206.09,95.98 206.33,95.74 217.15,95.74 217.49,96.08 217.49,97.13 217.17,97.45 206.27,97.45
N48270081 on L03_SIG1: 207.49,96.87 207.49,94.9 207.7,94.69 218.97,94.69 219.44,95.17 219.44,96.84 219.3,96.99 218.96,96.99 218.85,96.88 218.85,95.76 218.56,95.47 215.9,95.47 215.67,95.7 215.67,96.81 215.58,96.91 215.27,96.91 215.15,96.79 215.15,95.77 214.85,95.47 212.37,95.47 212.2,95.64 212.21,95.65 212.21,96.68 211.97,96.93 211.45,96.93 211.03,96.51 211.03,95.72 210.67,95.36 209.51,95.36 209.04,95.83 209.04,96.57 208.62,96.99 207.6,96.99
N48270097 on L03_SIG1: 206.2,97.5 206.95,97.5 207.11,97.65 207.11,99.66 207.43,99.98 209.73,99.98 209.92,99.8 209.92,98.03 210.12,97.83 210.55,97.83 210.81,98.09 210.81,99.86 210.95,100 213.44,100 213.63,99.81 213.63,98.08 213.91,97.8 214.35,97.8 214.51,97.95 214.51,97.99 214.66,98.14 214.66,99.7 214.9,99.94 217.38,99.94 217.5,99.81 217.5,98.05 217.74,97.81 218.3,97.81 218.46,97.97 218.46,100.65 218.07,101.04 206.47,101.04 206.01,100.57 206.01,97.69
N50006855 on TOP: 231.96,45.47 231.96,46.1 231.83,46.23 231.3,46.23 230.99,46.54 230.99,48.29 235.72,48.29 235.72,46.38 235.55,46.22 235.12,46.22 234.88,45.98 234.88,45.39 234.8,45.32 232.11,45.32

Small or netless copper shapes (teardrops, artwork), in the pictures only: 101 on TOP, 34 on BOTTOM

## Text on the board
BOTTOM: 100-0330695-B1 RevC1 | BOTTOM SIDE LAYER 18
Ref Des/Silkscreen Bottom: A | H | I | 2 | G | K | PCIE_EP_PRSNT | CLOSE-->SELECT | OPEN --> DESELECT | 8 | 5 | 11 | 10 | B | C | D | CLOSED = DISABLE | OPEN = ENABLE | X16 | X8 | X4 | X1 | 4 | 0 | 1 | MSEL | JTAG MASTER | Z | SW2 | Y | MSEL0 | MSEL1 | MSEL2 | JTAG | AVST x8 | Config Mode | A1 | J | 83 | F | E | 3 | 6 | 12 | 7 | 20 | 21 | 30 | 40 | P/N | 29 | 48 | 49 | 14 | MK | MF | 9 | A17 | A31 | A82 | 31 | A48 | S/N
User.Comments: CR_111111_33 | CR_111111_31 | CR_111111_29 | CR_111111_28 | CR_UNNAMED_68 | CR_111111_30 | CR_111111_22 | CR_1_6 | CR_123_1 | CR_111111_18 | CR_111111_19 | CR_UNNAMED_45 | CR_111111_24 | CR_111111_17 | CR_111111_25 | CR_111111_23 | CR_111111_27 | CR_11111_7 | CR_11111_8 | CR_111111_21 | CR_111111_26 | CR_111111_20 | CR_UNNAMED_27 | CR_UNNAMED1_2 | CR_UNNAMED_92 | CR_UNNAMED_44 | CR_U34_2 | CR_UNNAMED_48 | CR_UNNAMED_38 | CR_111111_1 | CR_UNNAMED_31 | CR_UNNAMED_32 | CR_UNNAMED1_1 | CR_UNNAMED1_3 | CR_UNNAMED_98 | CR_1_10 | CR_111111_45 | CR_UNNAMED_28 | CR_UNNAMED1_4 | CR_UNNAMED1_5 | CR_U34_1 | CR_UNNAMED_97 | CR_UNNAMED_36 | CR_11111_6 | CR_111111_2 | CR_123456_23 | CR_1_4 | CR_LTC7151SEV_1 | CR_123456_24 | CR_111111_3 | CR_123456_25 | CR_UNNAMED_55 | CR_UNNAMED_54 | CR_111111_51 | CR_111111_4 | CR_U30_3 | CR_LTC7151SEV_2 | CR_U32_2 | CR_22_1 | CR_22_2 | CR_DDR_DECAP_PLACE_1 | CR_U32_1 | CR_4444_1 | CR_11_2 | CR_123456_26 | CR_DECAP_1 | CR_DECAP_2 | CR_123456_27 | CR_UNNAMED_17 | CR_UNNAMED_56 | CR_UNNAMED_49 | CR_UNNAMED_23 | CR_Q4_3 | CR_U69_1 | CR_P3V3_2 | CR_U17_1 | CR_2_4 | CR_654321_5 | CR_Q4_2 | CR_UNNAMED_30 | CR_UNNAMED_26 | CR_654321_4 | CR_123456_28 | CR_UNNAMED_46 | CR_123456_19 | CR_UNNAMED_47 | CR_123456_29 | CR_UNNAMED_21 | CR_UNNAMED_22 | CR_123456_20 | CR_654321_3 | CR_111111_57 | CR_111111_56 | CR_123456_21 | CR_111111_55 | CR_111111_54 | CR_111111_52 | CR_123456_51 | CR_123456_52 | CR_UNNAMED_18 | CR_111111_36 | CR_S1_1 | CR_UNNAMED_104 | CR_UNNAMED_101 | CR_UNNAMED_103 | CR_UNNAMED_102 | CR_123456_11 | CR_123456_54 | CR_UNNAMED_61 | CR_111111_9 | CR_111111_37 | CR_123456_13 | CR_111111_7 | CR_111111_6 | CR_111111_10 | CR_111111_8 | CR_111111_35 | CR_123456_12 | CR_111111_40 | CR_1123_3 | CR_123456_14 | CR_123456_8 | CR_123456_15 | CR_111111_41 | CR_111111_32 | CR_UNNAMED_25 | CR_UNNAMED_39 | CR_UNNAMED_40 | CR_UNNAMED_41 | CR_UNNAMED_42 | CR_123456_17 | CR_123456_16 | CR_123456_37 | CR_1123_2 | CR_1123_1 | CR_111111_42 | CR_123456_56 | CR_UNNAMED_59 | CR_123456_3 | CR_111111_43 | CR_U139_1 | CR_UNNAMED_85 | CR_UNNAMED_86 | CR_1111111_2 | CR_2_1 | CR_111111_44 | CR_UNNAMED2_1 | CR_2_2 | CR_1111111_4 | CR_UNNAMED_29 | CR_111111_5 | CR_1111111_5 | CR_2_5 | CR_111111_12 | CR_1111111_7 | CR_Q4_5 | CR_1111111_6 | CR_M1_2 | CR_UNNAMED_37 | CR_PWR1_3 | CR_UNNAMED_74 | CR_1111111_9 | CR_333333_1 | CR_333333_2 | CR_1111111_10 | CR_1111111_1 | CR_1111_4 | CR_1234546_2 | CR_123456_39 | CR_111111_13 | CR_UNNAMED_50 | CR_123456_30 | CR_UNNAMED_83 | CR_UNNAMED2_2 | CR_123456_18 | CR_UNNAMED_24 | CR_123456_10 | CR_3_1 | CR_UNNAMED_53 | CR_UNNAMED_64 | CR_UNNAMED_63 | CR_UNNAMED_70 | CR_UNNAMED_69 | CR_UNNAMED_72 | CR_1123_6 | CR_1123_4 | CR_41_2 | CR_41_3 | CR_LTM4643_1 | CR_123456_40 | CR_PWR1_4 | CR_00_1 | CR_111111_59 | CR_111111_58 | CR_1111_2 | CR_111111_11 | CR_UNNAMED_77 | CR_UNNAMED_78 | CR_UNNAMED_79 | CR_444444_2 | CR_U69_2 | CR_Q4_4 | CR_Q4_6 | CR_11_7 | MEZZANINE MODULE | NOTES: UNLESS OTHERWISE SPECIFIED | 1.  ASSEMBLY BOARD PER IPC-A-610 (LATEST REVISION) STANDARD. | 2.  HANDLE MOISTURE SENSITIVE DEVICES(MSD) PER MANUFACTURE'S | CALL OUT ON MSD LABEL.  IF MSD LABEL IS MISSING OR NOT LEGIBLE | 3.  USE IPC-7711/7721 (LATEST REVISION) FOR ALL PCBA REWORK. | THEN ALL PLASTIC PACKAGED COMPONENTS ARE TO BE CONSIDERED MSD | LEVEL 6 AND USE EIA/JEP 113-A FOR HANDLING.
TOP: TOP SIDE LAYER 1
Ref Des/Silkscreen Top: R | G | Y | 56 | 43 | 42 | M | 12 | 14 | 29 | A | 16 | 15 | 28 | 4 | B | 10 | 6 | QSFPDD0 | D1 | D2 | D3 | QSFPDD1 | D4 | O | 5 | I | 32 | B1 | C | N | 3 | F | E | 25 | H | D | 33 | 17 | B17 | 7 | B31 | B48 | TM | B82 | L | J | S | K | B37 | P | EXTERNAL JTAG | A37 | CLK_OUT | CLK_IN | D11:FPGA_CONF_DONE | D9:OVERTEMPn | 8 | ADI DONGLE | 1 | POWER_INPUT | ON | OFF | FPGA_3V3 | 0 | 2 | POWER | T | 9 | 11 | 13 | 23 | 19 | 57 | 39 | 76 | 58 | 38 | 20 | 288 | 144 | 83 | 78 | 222 | 221 | 77 | MK | 145 | 22 | ADC_VREF | 31 | 40 | PWM | HSSI_PWM | TCK | TDO | TMS | TDI | GND | 12.5A | 12V_AUX | FX2_RESETn | PCIE_PERSTn | POWER_ON | FAN_CTRL | CPU_RESETn | GXF_PERSTn | CXL_PERSTn | Agilex  I-Series FPGA | DDR4 DUAL DIMM B | DDR4 DUAL DIMM A | 2LI
DIMENSION: R | 3X | 59.6 | 0.1339 | 0.0340 | 0.0551 | 0.0681 | 0.1585 | 0.2521 | 3.40 | 0.86 | 1.40 | 1.73 | 4.03 | 6.40 | 45 X.0200 | 45 X0.51 | 2X | 1.9 | .0748 | 2.74 | .1080 | 3.51 | .1380
PAGE_OUTLINE: THIS DOCUMENT CONTAINS PROPRIETARY INFORMATION | OF INTEL CORP. NEITHER THE DOCUMENT NOR SAID | PROPRIETARY INFORMATION SHALL BE PUBLISHED, | REPRODUCED, COPIED, DISCLOSED OR USED FOR ANY | PURPOSE OTHER THAN CONSIDERATION OF THIS DOCUMENT | WITHOUT THE EXPRESS WRITTEN PERMISSION OF A DULY | AUTHORIZED REPRESENTATIVE OF INTEL CORPORATION | PROPRIETARY NOTICE: | R | REV | B2
DISPLAY_BOTTOM: PLEASE ROMOVE CAPS | P25 | P66 | P16 | P9 | P68 | P75 | P57 | P44 | P26 | P30 | P64 | P67 | P11 | P10 | P71 | P58 | P72 | P14 | P52 | P45 | P55 | P65 | P76 | P43 | P73 | P59 | P15 | P49 | P50 | P51 | P27 | P38 | P56 | P69 | P63 | P74 | P20 | P21 | P32 | P70 | P28 | P39 | P23 | P33 | P35 | P47 | P77 | P46 | P18 | P29 | P13 | P61 | P54 | P24 | P34 | P37 | P31
